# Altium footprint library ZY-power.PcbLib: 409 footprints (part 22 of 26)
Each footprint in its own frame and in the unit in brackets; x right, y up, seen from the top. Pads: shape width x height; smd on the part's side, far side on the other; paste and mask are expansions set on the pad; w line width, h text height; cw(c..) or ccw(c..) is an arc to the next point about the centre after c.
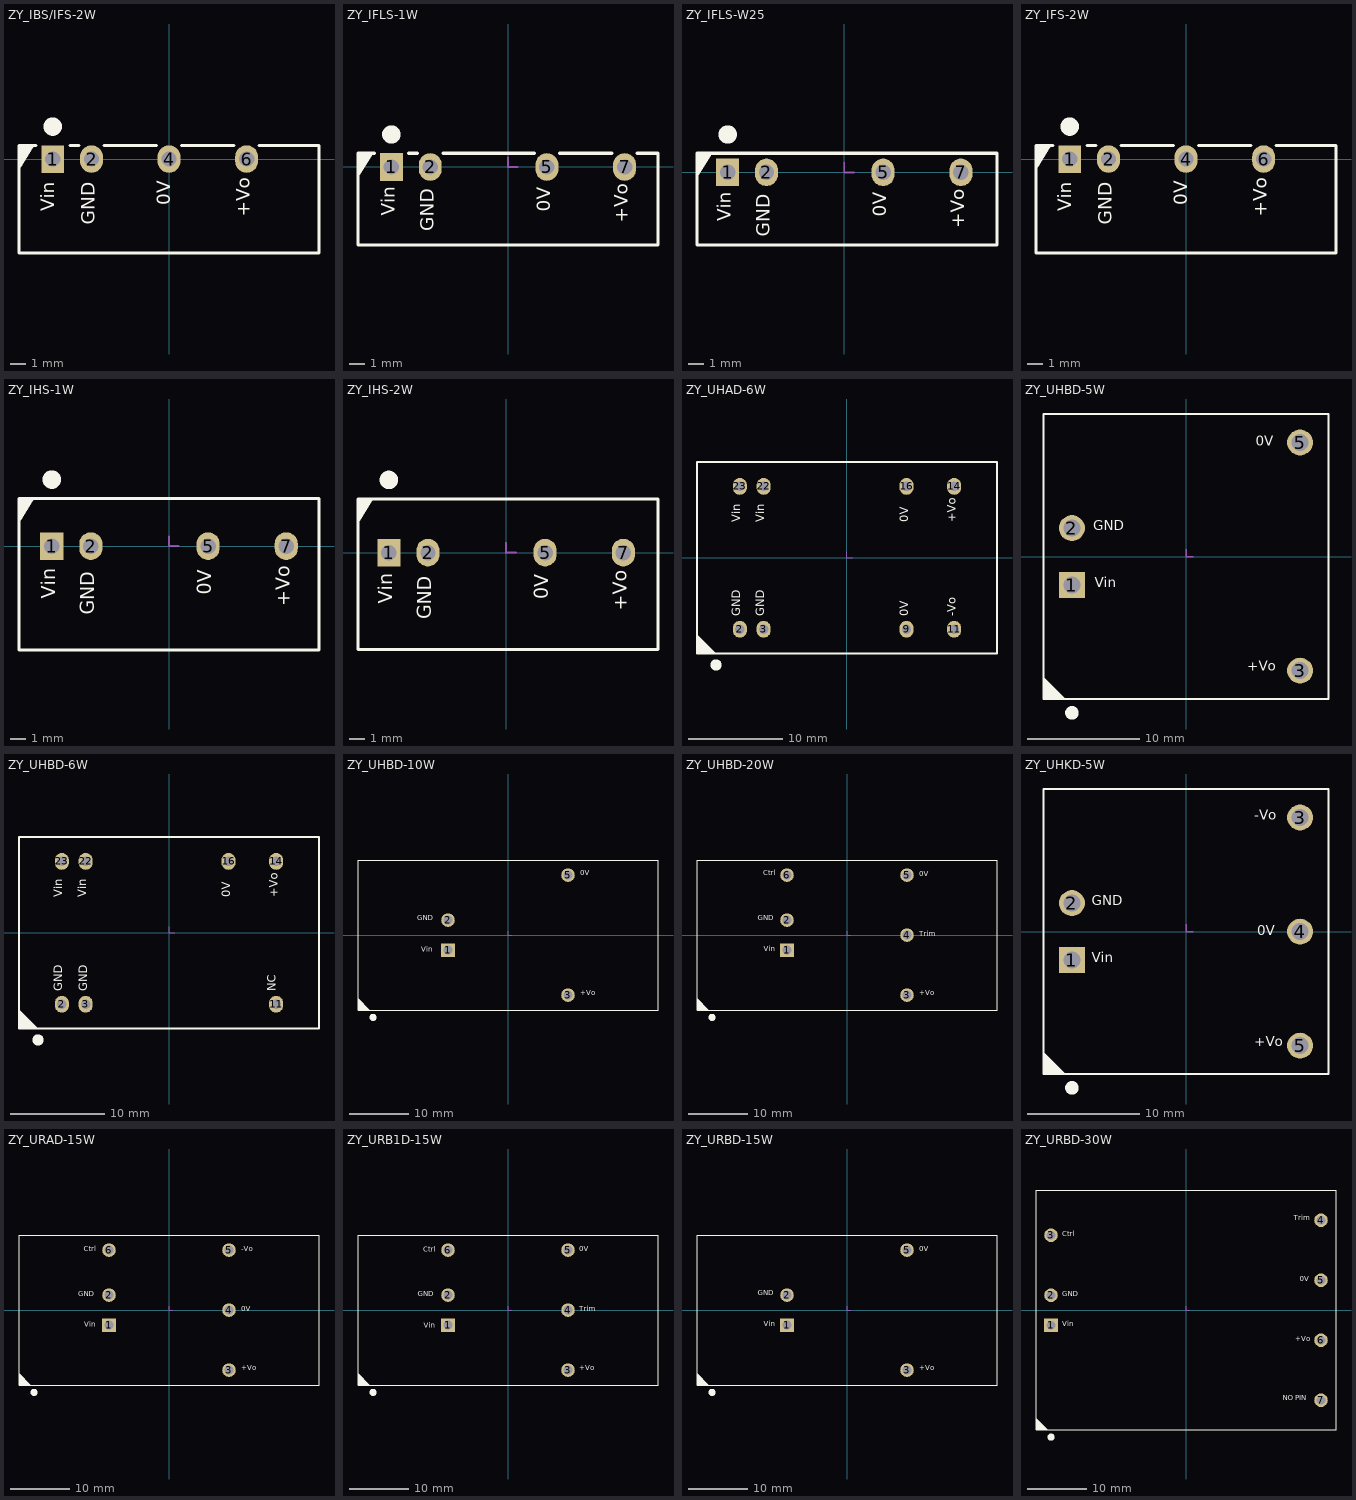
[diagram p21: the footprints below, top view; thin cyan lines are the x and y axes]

## ZY_IBS/IFS-2W [mm]
height 10.1
pads (4):
  rect 1.5x1.8 hole 1: 1(-7.62,0)
  oval 1.5x1.8 hole 1: 2(-5.08,0) 4(0,0) 6(5.08,0)
Top Overlay:
  circle w1: c-7.62,2.125 r0.1
  region: -9.83,-0.686 -9.83,0.9 -8.836,0.9
  lines w0.2: -8.72,0.9 -9.83,0.9 -9.83,-6.15 9.82,-6.15 9.82,0.9 5.9,0.9 ; -6.5,0.9 -5.9,0.9 ; -4.26,0.9 -0.82,0.9 ; 0.82,0.9 4.26,0.9
  text "Vin" at -7.239,-3.435 h1.52
  text "GND" at -4.572,-4.318 h1.52
  text "0V" at 0.381,-3.036 h1.52
  text "+Vo" at 5.588,-3.776 h1.52
Mechanical 15:
  lines w0.127: 0,0.635 0,0 0.635,0
3D body "zhenjao01.stp": height 8.36, standoff -4.08, extent -8.32,-1.48 -6.92,0.12
3D body "zhenjao01.stp": height 8.36, standoff -4.08, extent -5.78,-1.48 -4.38,0.12
3D body "zhenjao01.stp": height 8.36, standoff -4.08, extent -0.7,-1.48 0.7,0.12
3D body "zhenjao01.stp": height 8.36, standoff -4.08, extent 4.38,-1.48 5.78,0.12
3D body: height 10.1, standoff 0, extent -9.83,-6.15 9.77,0.9

## ZY_IFLS-1W [mm]
height 10.1
pads (4):
  rect 1.5x1.8 hole 1: 1(-7.62,0)
  oval 1.5x1.8 hole 1: 2(-5.08,0) 5(2.54,0) 7(7.62,0)
Top Overlay:
  circle w1: c-7.62,2.125 r0.1
  region: -9.8,-0.686 -9.8,0.9 -8.806,0.9
  lines w0.2: -8.72,0.9 -9.8,0.9 -9.8,-5.1 9.8,-5.1 9.8,0.9 8.44,0.9 ; -6.5,0.9 -5.9,0.9 ; -4.26,0.9 1.72,0.9 ; 3.36,0.9 6.8,0.9
  text "Vin" at -7.112,-3.181 h1.52
  text "GND" at -4.572,-4.191 h1.52
  text "0V" at 3.048,-2.909 h1.52
  text "+Vo" at 8.128,-3.649 h1.52
Mechanical 15:
  lines w0.127: 0,0.635 0,0 0.635,0
3D body "zhenjao01.stp": height 8.36, standoff -4.08, extent -8.32,-1.48 -6.92,0.12
3D body "zhenjao01.stp": height 8.36, standoff -4.08, extent -5.78,-1.48 -4.38,0.12
3D body "zhenjao01.stp": height 8.36, standoff -4.08, extent 1.84,-1.48 3.24,0.12
3D body "zhenjao01.stp": height 8.36, standoff -4.08, extent 6.92,-1.48 8.32,0.12
3D body: height 10.1, standoff 0, extent -9.8,-5.1 9.8,0.9

## ZY_IFLS-W25 [mm]
pads (4):
  rect 1.5x1.8 hole 1: 1(-7.62,0)
  oval 1.5x1.8 hole 1: 2(-5.08,0) 5(2.54,0) 7(7.62,0)
Top Overlay:
  circle w1: c-7.62,2.475 r0.1
  region: -9.62,-0.336 -9.62,1.25 -8.626,1.25
  lines w0.2: -9.62,-4.75 9.98,-4.75 9.98,1.25 -9.62,1.25 -9.62,-4.75
  text "+Vo" at 8.128,-3.649 h1.52
  text "0V" at 3.048,-2.909 h1.52
  text "GND" at -4.572,-4.191 h1.52
  text "Vin" at -7.112,-3.181 h1.52
Mechanical 15:
  lines w0.127: 0,0.635 0,0 0.635,0

## ZY_IFS-2W [mm]
height 10.1
pads (4):
  rect 1.5x1.8 hole 1: 1(-7.62,0)
  oval 1.5x1.8 hole 1: 2(-5.08,0) 4(0,0) 6(5.08,0)
Top Overlay:
  circle w1: c-7.62,2.125 r0.1
  region: -9.83,-0.686 -9.83,0.9 -8.836,0.9
  lines w0.2: -8.72,0.9 -9.83,0.9 -9.83,-6.15 9.82,-6.15 9.82,0.9 5.9,0.9 ; -6.5,0.9 -5.9,0.9 ; -4.26,0.9 -0.82,0.9 ; 0.82,0.9 4.26,0.9
  text "Vin" at -7.239,-3.435 h1.52
  text "GND" at -4.572,-4.318 h1.52
  text "0V" at 0.381,-3.036 h1.52
  text "+Vo" at 5.588,-3.776 h1.52
Mechanical 15:
  lines w0.127: 0,0.635 0,0 0.635,0
3D body "zhenjao01.stp": height 8.36, standoff -4.08, extent -8.32,-1.48 -6.92,0.12
3D body "zhenjao01.stp": height 8.36, standoff -4.08, extent -5.78,-1.48 -4.38,0.12
3D body "zhenjao01.stp": height 8.36, standoff -4.08, extent -0.7,-1.48 0.7,0.12
3D body "zhenjao01.stp": height 8.36, standoff -4.08, extent 4.38,-1.48 5.78,0.12
3D body: height 10.1, standoff 0, extent -9.83,-6.15 9.77,0.9

## ZY_IHS-1W [mm]
height 12.5
pads (4):
  rect 1.5x1.8 hole 1: 1(-7.62,0)
  oval 1.5x1.8 hole 1: 2(-5.08,0) 5(2.54,0) 7(7.62,0)
Top Overlay:
  circle w1: c-7.62,4.325 r0.1
  region: -9.75,1.504 -9.75,3.1 -8.75,3.1
  lines w0.2: -9.75,-6.75 9.75,-6.75 9.75,3.1 -9.75,3.1 -9.75,-6.75
  text "+Vo" at 8.128,-3.903 h1.52
  text "0V" at 3.048,-3.163 h1.52
  text "GND" at -4.572,-4.445 h1.52
  text "Vin" at -7.112,-3.435 h1.52
Mechanical 15:
  lines w0.127: 0,0.635 0,0 0.635,0
3D body: height 12.5, standoff 0, extent -9.75,-6.75 9.75,3.1
3D body "zhenjao01.stp": height 8.36, standoff -4.08, extent 6.92,-1.48 8.32,0.12
3D body "zhenjao01.stp": height 8.36, standoff -4.08, extent 1.84,-1.48 3.24,0.12
3D body "zhenjao01.stp": height 8.36, standoff -4.08, extent -5.78,-1.48 -4.38,0.12
3D body "zhenjao01.stp": height 8.36, standoff -4.08, extent -8.32,-1.48 -6.92,0.12

## ZY_IHS-2W [mm]
height 12.5
pads (4):
  rect 1.5x1.8 hole 1: 1(-7.62,0)
  oval 1.5x1.8 hole 1: 2(-5.08,0) 5(2.533,0) 7(7.62,0)
Top Overlay:
  circle w1: c-7.62,4.725 r0.1
  region: -9.62,1.914 -9.62,3.5 -8.626,3.5
  lines w0.2: 9.873,3.45 9.873,-6.3 -9.627,-6.3 -9.627,3.5 9.873,3.5
  text "+Vo" at 8.128,-3.776 h1.52
  text "0V" at 3.048,-3.036 h1.52
  text "GND" at -4.572,-4.318 h1.52
  text "Vin" at -7.112,-3.308 h1.52
Mechanical 15:
  lines w0.127: 0,0.635 0,0 0.635,0

## ZY_UHAD-6W [mm]
height 10.5
pads (8):
  oval 1.5x1.8 hole 1: 2(-11.43,-7.62) 3(-8.89,-7.62) 9(6.35,-7.62) 11(11.43,-7.62) 14(11.43,7.62) 16(6.35,7.62) 22(-8.89,7.62) 23(-11.43,7.62)
Top Overlay:
  circle w1: c-13.97,-11.425 r0.1
  region: -16,-10.2 -14.025,-10.2 -16,-8.225
  lines w0.2: -16,-10.2 16,-10.2 16,10.2 -16,10.2 -16,-10.2
  text "0V" at 6.858,3.81 h1.52
  text "+Vo" at 11.938,3.81 h1.52
  text "-Vo" at 11.938,-6.223 h1.52
  text "Vin" at -8.509,3.81 h1.52
  text "Vin" at -11.049,3.81 h1.52
  text "GND" at -8.509,-6.223 h1.52
  text "GND" at -11.049,-6.223 h1.52
  text "0V" at 6.858,-6.223 h1.52
Mechanical 15:
  lines w0.127: 0,0.635 0,0 0.635,0

## ZY_UHBD-5W [mm]
height 11.7
pads (4):
  rect 2.3x2.3 hole 1.5: 1(-10.16,-2.54)
  round 2.3 hole 1.5: 2(-10.16,2.54) 3(10.16,-10.16) 5(10.16,10.16)
Top Overlay:
  circle w1: c-10.16,-13.925 r0.1
  region: -12.7,-12.7 -10.725,-12.7 -12.7,-10.725
  lines w0.2: -12.7,-12.7 12.7,-12.7 12.7,12.7 -12.7,12.7 -12.7,-12.7
  text "0V" at 6.201,9.576 h1.52
  text "+Vo" at 5.461,-10.49 h1.52
  text "Vin" at -8.128,-3.048 h1.52
  text "GND" at -8.255,2.032 h1.52
Mechanical 15:
  lines w0.127: 0,0.635 0,0 0.635,0

## ZY_UHBD-6W [mm]
height 10.5
pads (7):
  oval 1.5x1.8 hole 1: 2(-11.43,-7.62) 3(-8.89,-7.62) 11(11.43,-7.62) 14(11.43,7.62) 16(6.35,7.62) 22(-8.89,7.62) 23(-11.43,7.62)
Top Overlay:
  circle w1: c-13.97,-11.425 r0.1
  region: -16,-10.2 -14.025,-10.2 -16,-8.225
  lines w0.2: -16,-10.2 16,-10.2 16,10.2 -16,10.2 -16,-10.2
  text "0V" at 6.858,3.81 h1.52
  text "+Vo" at 11.938,3.81 h1.52
  text "NC" at 11.684,-6.223 h1.52
  text "Vin" at -8.509,3.81 h1.52
  text "Vin" at -11.049,3.81 h1.52
  text "GND" at -8.382,-6.223 h1.52
  text "GND" at -11.049,-6.223 h1.52
Mechanical 15:
  lines w0.127: 0,0.635 0,0 0.635,0

## ZY_UHBD-10W [mm]
height 12.7
pads (4):
  rect 2.3x2.3 hole 1.5: 1(-10.16,-2.54)
  round 2.3 hole 1.5: 2(-10.16,2.54) 3(10.16,-10.16) 5(10.16,10.16)
Top Overlay:
  circle w1: c-22.86,-13.925 r0.1
  region: -25.4,-12.7 -23.425,-12.7 -25.4,-10.725
  lines w0.2: -25.4,-12.7 25.4,-12.7 25.4,12.7 -25.4,12.7 -25.4,-12.7
  text "0V" at 12.192,9.779 h1.52
  text "+Vo" at 12.192,-10.541 h1.52
  text "GND" at -15.368,2.159 h1.52
  text "Vin" at -14.732,-3.175 h1.52
Mechanical 15:
  lines w0.127: 0,0.635 0,0 0.635,0

## ZY_UHBD-20W [mm]
pads (6):
  rect 2.3x2.3 hole 1.5: 1(-10.16,-2.54)
  round 2.3 hole 1.5: 2(-10.16,2.54) 3(10.16,-10.16) 4(10.16,0) 5(10.16,10.16) 6(-10.16,10.16)
Top Overlay:
  circle w1: c-22.86,-13.925 r0.1
  region: -25.4,-12.7 -23.425,-12.7 -25.4,-10.725
  lines w0.2: -25.4,-12.7 25.4,-12.7 25.4,12.7 -25.4,12.7 -25.4,-12.7
  text "Ctrl" at -14.187,9.779 h1.52
  text "Trim" at 12.192,-0.508 h1.52
  text "Vin" at -14.103,-3.048 h1.52
  text "GND" at -15.113,2.159 h1.52
  text "0V" at 12.192,9.652 h1.52
  text "+Vo" at 12.192,-10.541 h1.52
Mechanical 15:
  lines w0.127: 0,0.635 0,0 0.635,0

## ZY_UHKD-5W [mm]
pads (5):
  rect 2.3x2.3 hole 1.5: 1(-10.16,-2.54)
  round 2.3 hole 1.5: 2(-10.16,2.54) 3(10.16,10.16) 4(10.16,0) 5(10.16,-10.16)
Top Overlay:
  circle w1: c-10.16,-13.925 r0.1
  region: -12.7,-12.7 -10.725,-12.7 -12.7,-10.725
  lines w0.2: -12.7,-12.7 12.7,-12.7 12.7,12.7 -12.7,12.7 -12.7,-12.7
  text "+Vo" at 6.096,-10.541 h1.52
  text "-Vo" at 6.096,9.652 h1.52
  text "0V" at 6.35,-0.635 h1.52
  text "GND" at -8.382,2.032 h1.52
  text "Vin" at -8.382,-3.048 h1.52
Mechanical 15:
  lines w0.127: 0,0.635 0,0 0.635,0

## ZY_URAD-15W [mm]
pads (6):
  rect 2.3x2.3 hole 1.5: 1(-10.16,-2.54)
  round 2.3 hole 1.5: 2(-10.16,2.54) 3(10.16,-10.16) 4(10.16,0) 5(10.16,10.16) 6(-10.16,10.16)
Top Overlay:
  circle w1: c-22.86,-13.925 r0.1
  region: -25.4,-12.7 -23.425,-12.7 -25.4,-10.725
  lines w0.2: -25.4,-12.7 -25.4,12.7 25.4,12.7 25.4,-12.7 -25.4,-12.7
  text "+Vo" at 12.192,-10.541 h1.52
  text "-Vo" at 12.192,9.652 h1.52
  text "GND" at -15.368,2.032 h1.52
  text "Vin" at -14.358,-3.175 h1.52
  text "0V" at 12.192,-0.508 h1.52
  text "Ctrl" at -14.443,9.652 h1.52
Mechanical 15:
  lines w0.127: 0,0.635 0,0 0.635,0

## ZY_URB1D-15W [mm]
pads (6):
  rect 2.3x2.3 hole 1.5: 1(-10.16,-2.54)
  round 2.3 hole 1.5: 2(-10.16,2.54) 3(10.16,-10.16) 4(10.16,0) 5(10.16,10.16) 6(-10.16,10.16)
Top Overlay:
  circle w1: c-22.86,-13.925 r0.1
  region: -25.4,-12.7 -23.425,-12.7 -25.4,-10.725
  lines w0.2: -25.4,-12.7 25.4,-12.7 25.4,12.7 -25.4,12.7 -25.4,-12.7
  text "Ctrl" at -14.316,9.525 h1.52
  text "Trim" at 12.065,-0.508 h1.52
  text "Vin" at -14.231,-3.302 h1.52
  text "GND" at -15.241,2.032 h1.52
  text "0V" at 12.065,9.652 h1.52
  text "+Vo" at 12.065,-10.541 h1.52
Mechanical 15:
  lines w0.127: 0,0.635 0,0 0.635,0

## ZY_URBD-15W [mm]
pads (4):
  rect 2.3x2.3 hole 1.5: 1(-10.16,-2.54)
  round 2.3 hole 1.5: 2(-10.16,2.54) 3(10.16,-10.16) 5(10.16,10.16)
Top Overlay:
  circle w1: c-22.86,-13.925 r0.1
  region: -25.4,-12.7 -23.425,-12.7 -25.4,-10.725
  lines w0.2: -25.4,-12.7 25.4,-12.7 25.4,12.7 -25.4,12.7 -25.4,-12.7
  text "Vin" at -14.104,-3.048 h1.52
  text "GND" at -15.114,2.159 h1.52
  text "0V" at 12.192,9.652 h1.52
  text "+Vo" at 12.192,-10.541 h1.52
Mechanical 15:
  lines w0.127: 0,0.635 0,0 0.635,0

## ZY_URBD-30W [mm]
height 12.5
pads (7):
  rect 2.3x2.3 hole 1.5: 1(-22.86,-2.54)
  round 2.3 hole 1.5: 2(-22.86,2.54) 3(-22.86,12.7) 4(22.86,15.24) 5(22.86,5.08) 6(22.86,-5.08) 7(22.86,-15.24)
Top Overlay:
  circle w1: c-22.86,-21.505 r0.1
  region: -25.4,-20.28 -23.425,-20.28 -25.4,-18.305
  lines w0.2: -25.4,-20.28 -25.4,20.32 25.4,20.32 25.4,-20.28 -25.4,-20.28
  text "NO PIN" at 16.383,-15.621 h1.52
  text "GND" at -20.955,2.052 h1.52
  text "Trim" at 18.255,14.879 h1.52
  text "Ctrl" at -20.955,12.212 h1.52
  text "0V" at 19.263,4.592 h1.52
  text "+Vo" at 18.523,-5.568 h1.52
  text "Vin" at -20.955,-3.028 h1.52
Mechanical 15:
  lines w0.127: 0,0.635 0,0 0.635,0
